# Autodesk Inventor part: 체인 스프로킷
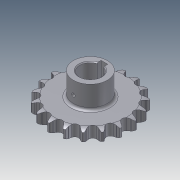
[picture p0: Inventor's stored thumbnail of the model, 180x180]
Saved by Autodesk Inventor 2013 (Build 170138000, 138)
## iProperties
Created: 2014-07
Part Number: 체인 스프로킷
Material: 강
Document SubType Name: Modeling
Designer: KYOUNG IL JANG
Density: 1 g/cm^3
CustomPartVersion: 1
Company: 한국ATC센터
Author: KYOUNG IL JANG
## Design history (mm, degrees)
sketch "이론적 톱니 프로파일"
  geometry: L1 (0, 0)-(0, 45.567); L2 (0, 0)-(14.795, 43.098); L3 (0, 45.567)-(14.795, 43.098); L4 (0, 45.567)-(5.661, 50.015); L5 (5.661, 50.015)-(-5.141, 45.406); L6 (-12.428, 43.493)-(-5.573, 46.417); L7 (-5.141, 45.406)-(-5.573, 46.417); L8 (5.573, 46.417)-(5.141, 45.406); L9 (0, 0)-(8.138, 48.771); A1 r 45.567 centre (0, 0) between (0, 45.567) and (14.795, 43.098); A2 r 49.445 centre (0, 0) between (7.302, 48.903) and (-7.302, 48.903); A3 r 4.545 centre (0, 45.567) between (-3.574, 42.758) and (3.574, 42.758); A4 r 7.453 centre (12.428, 43.493) between (7.302, 48.903) and (5.573, 46.417); A5 r 7.453 centre (-12.428, 43.493) between (-5.573, 46.417) and (-7.302, 48.903); A6 r 11.745 centre (5.661, 50.015) between (-5.141, 45.406) and (-3.574, 42.758); A7 r 11.745 centre (-5.661, 50.015) between (3.574, 42.758) and (5.141, 45.406); 2 further points
  constraints: 18 end point, 15 point on circle, 7 centre point, 3 coincident, 3 point on line, 3 symmetric about line, 3 tangent, 1 equal radius, 1 midpoint, 1 parallel, 1 vertical, 1 other
  dimensions: "d0" = 91.13301 diameter of A1 (computed from da_p, da_z); "d2" = 18.9474 deg angle of L2 L1 (computed from da_z); "d3" = 4.545 radius of A3 (= 0.5 x da_Dr + da_SC); "d10" = 128.158 deg angle of L4 L1 (computed from da_z); "d11" = 15.0526 deg angle of L5 L4 (computed from da_z); "d12" = 7.2 distance of L3.start L4.end (= 0.8 x da_Dr); "d13" = 11.745 distance of L4.end L5.end (= 1.3 x da_Dr + da_SC); "d14" = 12.6 distance of A4.centre L1.end (= 1.4 x da_Dr); "d23" = 4.5 distance from line of L9.end L3 (= da_Ha)
sketch "톱니 프로파일"
  geometry: L1 (0, 0)-(0, 45.567); L2 (0, 45.567)-(4.203, 43.837); L3 (0, 45.567)-(-4.203, 43.837); A1 r 4.545 centre (0, 45.567) between (-4.203, 43.837) and (4.203, 43.837); A2 r 22.68 centre (25.176, 35.206) between (7.12, 48.93) and (4.203, 43.837); A3 r 22.68 centre (-25.176, 35.206) between (-4.203, 43.837) and (-7.12, 48.93); A4 r 49.445 centre (0, 0) between (-7.12, 48.93) and (7.12, 48.93) reference; 1 further point
  constraints: 9 point on circle, 6 end point, 3 centre point, 2 tangent, 1 coincident, 1 equal radius, 1 vertical, 1 other
  dimensions: "d44" = 135.263 deg angle of L3 L2 (= da_Alfa); "d45" = 22.68 radius of A2 (= da_Re); "d46" = 4.545 radius of A1 (= da_Ri)
sketch "단면 프로파일"
  geometry: L1 (49.445, 0)-(-49.445, 0) reference; L2 (33.265, 6.65)-(-33.265, 6.65); L3 (-33.265, 6.65)-(-33.265, -6.65); L4 (-33.265, -6.65)-(33.265, -6.65); L5 (33.265, -6.65)-(33.265, 6.65); L6 (33.265, 6.65)-(49.445, 6.65); L7 (49.445, 6.65)-(49.445, -6.65); L8 (49.445, -6.65)-(33.265, -6.65); L9 (33.265, -6.65)-(33.265, 6.65); L10 (42.183, 6.65)-(0, 6.65); L11 (0, 6.65)-(0, -6.65); L12 (0, -6.65)-(42.183, -6.65); L13 (0, 6.65)-(0, -6.65); L14 (49.445, 4.775)-(49.445, -4.775); A1 r 15 centre (42.183, -8.35) between (49.445, 4.775) and (42.183, 6.65); A2 r 15 centre (42.183, 8.35) between (42.183, -6.65) and (49.445, -4.775); 2 further points
  constraints: 26 end point, 7 midpoint, 5 perpendicular, 4 parallel, 4 point on circle, 3 point on line, 3 symmetric about line, 2 centre point, 2 horizontal, 2 tangent, 1 collinear, 1 other
  dimensions: "d30" = 13.3 distance between parallel lines of L8 L6 (= da_Bf); "d31" = 66.53007 distance between parallel lines of L3 L5 (= da_Ds); "d32" = 13.3 distance between parallel lines of L4 L2 (= da_Bs); "d33" = 1.875 distance from line of L14.start L6 (= da_Ba); "d34" = 15 radius of A1 (= da_Rx); "d43" = 6.65 distance between parallel lines of L4 L1 (computed from da_k, da_pt, da_Bs)
revolve "슈라우드" stored, may be unused: angle "d36" = 90 deg
revolve "스트랜드" stored, may be unused: angle "d37" = 90 deg
extrude "이론적 톱니" cut sketch "이론적 톱니 프로파일" stored distance "d18" = 10; taper "d19" = 0 deg; dims "d49" = 0, "form_type" = 0 [user parameter]
extrude "톱니" cut sketch "톱니 프로파일" stored distance "d47" = 10; taper "d48" = 0 deg; dims "d50" = 10, "form_type" = 0 [user parameter]
node "타이밍 평면"
node "작업 평면3"
sketch "스케치5"
  geometry: C1 r 20 at (0, -45.567); 1 further point
  constraints: 1 centre point, 1 coincident
  dimensions: "d52" = 40 diameter of C1
extrude "돌출4" join sketch "스케치5" stored distance "d53" = 10; taper "d54" = 0 deg
sketch "스케치6"
  geometry: L1 (4, 11.843)-(4, 16.5); L2 (4, 16.5)-(-4, 16.5); L3 (-4, 16.5)-(-4, 11.843); A1 r 12.5 centre (0, 0) between (4, 11.843) and (-4, 11.843); 1 further point
  constraints: 6 end point, 2 parallel, 2 point on circle, 1 centre point, 1 coincident, 1 perpendicular, 1 vertical
  dimensions: "d55" = 25 diameter of A1; "d56" = 29 dimension on A1 L2 (computed from d55); "d57" = 8 distance of L1.end L2.end
extrude "돌출5" cut sketch "스케치6" stored distance "d58" = 10; taper "d59" = 0 deg
fillet "모깎기2" dims "d60" = 3
chamfer "모따기1" distance "d61" = 1; stored, may be unused: second distance "d62" = 2, angle "d63" = 45 deg
node "작업 평면4"
sketch "스케치7"
  geometry: L1 (-13.5, -13.3)-(13.5, -13.3) reference; 4 further points
  constraints: 1 vertical alignment
  dimensions: "d65" = 25 distance from line of point (0, 11.7) L1
hole "구멍1" sketch "스케치7" at (0, 11.7) diameter "d66" = 4.134; stored, may be unused: countersink angle "d70" = 90 deg, drill point angle "d72" = 118 deg; dims "d67" = 6, "d68" = 4, "d69" = 2, "d71" = 8
body "Solid1"
pattern_linear "스트랜드 패턴" dims "d40" = 24 (= da_pt)
pattern_circular "톱니 패턴" dims angle "d21" = 360 deg
other parameters: "da_p" = 15 [user parameter; used in 1 equation term], "da_Dr" = 9 [user parameter; used in 4 equation terms], "da_SC" = 0.045 [user parameter; used in 2 equation terms], "da_Ha" = 4.5 [user parameter; used in 1 equation term], "da_pt" = 24 [user parameter; used in 2 equation terms], "da_Bf" = 13.3 [user parameter; used in 1 equation term], "d28" = 0, "d29" = 0, "da_Ba" = 1.875 [user parameter; used in 1 equation term], "da_Rx" = 15 [user parameter; used in 1 equation term], "da_Ra" = 0.6 [user parameter], "da_Bs" = 13.3 [user parameter; used in 2 equation terms], "da_Ds" = 66.53007 [user parameter; used in 1 equation term], "d42" = 0, "da_Re" = 22.68 [user parameter; used in 1 equation term], "da_Ri" = 4.545 [user parameter; used in 1 equation term], "da_Alfa" = 135.263 deg [user parameter; used in 1 equation term]
